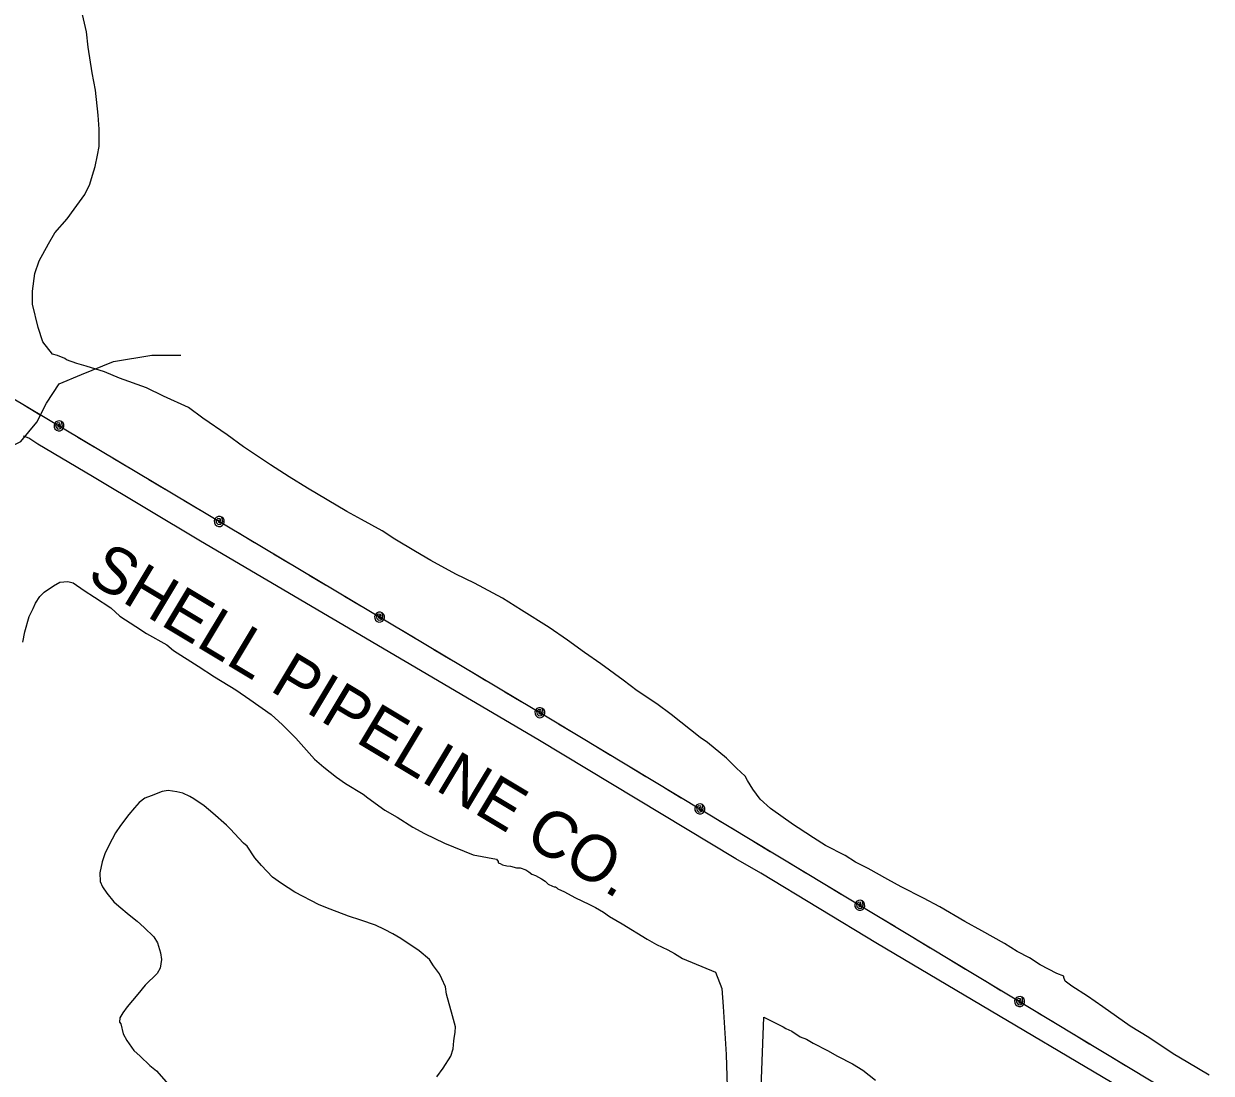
# Model space of a CAD drawing. Extents: x 3355677 to 3393573, y 612928 to 638357.
# Drawn here: x 3382938 to 3385063, y 630906 to 632784 of the extents above; entities that cross this region are included whole.
import ezdxf

# ---------------------------------------------------------------- set-up
doc = ezdxf.new("R2010")
doc.units = 0
for name, color, linetype in [('V-ROAD-CNTR', 7, 'Continuous'), ('V-SITE-VEGE', 7, 'Continuous'), ('V-TOPO-SHOR', 7, 'Continuous'), ('V-UTIL-IDEN', 7, 'Continuous'), ('V-UTIL-LINE', 7, 'Continuous')]:
    doc.layers.add(name, color=color, linetype=linetype)

msp = doc.modelspace()

# ---------------------------------------------------------------- linework, layer by layer
at = {"layer": 'V-ROAD-CNTR'}
msp.add_spline([(3382717.9, 631509.3), (3382683, 631774.7), (3382645.6, 632061.1), (3382613.4, 632280.7), (3382607, 632336.9), (3382604.4, 632398.7), (3382603.4, 632508.7), (3382612.3, 632627.6), (3382654.5, 632927.5), (3382669.5, 633023.9), (3382682.6, 633148.8), (3382689, 633232), (3382692.9, 633407.4), (3382698.9, 633498.5), (3382707.2, 633527.5), (3382719.2, 633555.1), (3382736.7, 633581.7), (3382777.9, 633615.1), (3383029.9, 633741), (3383294, 633867.7), (3383400.4, 633901.1), (3383469.4, 633903.2), (3383518.6, 633883.7), (3383607.6, 633824.8), (3383746.8, 633756.4), (3383797.6, 633735.9), (3383849.3, 633690.5), (3383896.6, 633650.2), (3383949.4, 633607.3), (3384007.3, 633569.4), (3384064.9, 633557.2), (3384119.3, 633550.6), (3384167.5, 633588.4), (3384178.7, 633673.8), (3384210.8, 633866.5), (3384225.9, 634112.9), (3384238.7, 634424.3), (3384250.9, 634776.1), (3384254, 634833.1)], degree=3, dxfattribs=at)
at = {"layer": 'V-SITE-VEGE'}
for p, q in [((3383050.1, 632770.1), (3383042.9, 632800.9)), ((3383053, 632742.7), (3383050.1, 632770.1)), ((3383060.1, 632696.5), (3383053, 632742.7)), ((3383066.2, 632665.7), (3383060.1, 632696.5)), ((3383071.1, 632620.7), (3383066.2, 632665.7)), ((3383072.9, 632595.5), (3383071.1, 632620.7)), ((3383072.5, 632564.8), (3383072.9, 632595.5)), ((3383070, 632549.4), (3383072.5, 632564.8)), ((3383065.4, 632528.7), (3383070, 632549.4)), ((3383060.8, 632513.4), (3383065.4, 632528.7)), ((3383047.1, 632478.5), (3383056.1, 632497)), ((3383056.1, 632497), (3383060.8, 632513.4)), ((3383028.1, 632452.5), (3383047.1, 632478.5)), ((3382993.5, 632410.2), (3383015.8, 632435.1)), ((3383015.8, 632435.1), (3383028.1, 632452.5)), ((3382965.4, 632360.2), (3382982.3, 632390.6)), ((3382982.3, 632390.6), (3382993.5, 632410.2)), ((3382957.4, 632337.2), (3382965.4, 632360.2)), ((3382953.7, 632305.5), (3382957.4, 632337.2)), ((3382953.3, 632282.5), (3382953.7, 632305.5)), ((3382963.7, 632240.7), (3382953.3, 632282.5)), ((3382972.1, 632215.3), (3382963.7, 632240.7)), ((3382989.4, 632193.2), (3382972.1, 632215.3)), ((3382998.1, 632190.8), (3382989.4, 632193.2)), ((3383011.2, 632185.2), (3382998.1, 632190.8)), ((3383014.4, 632182.9), (3383011.2, 632185.2)), ((3383033, 632176.1), (3383014.4, 632182.9)), ((3383049.3, 632171.5), (3383033, 632176.1)), ((3383082.1, 632161.2), (3383049.3, 632171.5)), ((3383109.3, 632149.8), (3383082.1, 632161.2)), ((3383157.3, 632132.7), (3383109.3, 632149.8)), ((3383187.8, 632118), (3383157.3, 632132.7)), ((3383232.5, 632097.6), (3383187.8, 632118)), ((3383258.5, 632078.6), (3383232.5, 632097.6)), ((3383302, 632048.4), (3383258.5, 632078.6)), ((3383331.3, 632027.2), (3383302, 632048.4)), ((3383379.1, 631994.7), (3383331.3, 632027.2)), ((3383412.7, 631973.4), (3383379.1, 631994.7)), ((3383445.3, 631953.2), (3383412.7, 631973.4)), ((3383516, 631911.6), (3383445.3, 631953.2)), ((3383542.1, 631897), (3383516, 631911.6)), ((3383579.1, 631876.7), (3383542.1, 631897)), ((3383601.9, 631862.2), (3383579.1, 631876.7)), ((3383638.9, 631839.7), (3383601.9, 631862.2)), ((3383666.1, 631824), (3383638.9, 631839.7)), ((3383710.7, 631799.2), (3383666.1, 631824)), ((3383744.5, 631783.4), (3383710.7, 631799.2)), ((3383794.5, 631756.4), (3383744.5, 631783.4)), ((3383828.2, 631735.1), (3383794.5, 631756.4)), ((3383878.2, 631703.7), (3383828.2, 631735.1)), ((3383910.8, 631681.3), (3383878.2, 631703.7)), ((3383941.1, 631658.9), (3383910.8, 631681.3)), ((3383970.5, 631638.8), (3383941.1, 631658.9)), ((3384010.6, 631609.7), (3383970.5, 631638.8)), ((3384035.6, 631590.7), (3384010.6, 631609.7)), ((3384070.3, 631567.2), (3384035.6, 631590.7)), ((3384096.3, 631548.2), (3384070.3, 631567.2)), ((3384148.4, 631506.9), (3384096.3, 631548.2)), ((3384161.4, 631497.9), (3384148.4, 631506.9)), ((3384195, 631470), (3384161.4, 631497.9)), ((3384213.4, 631452.2), (3384195, 631470)), ((3384228.5, 631437.8), (3384213.4, 631452.2)), ((3384232.8, 631430), (3384228.5, 631437.8)), ((3384242.5, 631414.5), (3384232.8, 631430)), ((3384255.4, 631396.8), (3384242.5, 631414.5)), ((3384273.8, 631380.1), (3384255.4, 631396.8)), ((3384315, 631351), (3384273.8, 631380.1)), ((3384323.7, 631345.4), (3384315, 631351)), ((3384350.9, 631327.5), (3384323.7, 631345.4)), ((3384372.6, 631314), (3384350.9, 631327.5)), ((3384407.4, 631296), (3384372.6, 631314)), ((3384425.9, 631283.7), (3384407.4, 631296)), ((3384448.8, 631272.4), (3384425.9, 631283.7)), ((3384483.6, 631253.2), (3384448.8, 631272.4)), ((3384507.5, 631239.7), (3384483.6, 631253.2)), ((3384547.8, 631219.4), (3384507.5, 631239.7)), ((3384577.2, 631203.7), (3384547.8, 631219.4)), ((3384621.8, 631177.8), (3384577.2, 631203.7)), ((3384652.2, 631161), (3384621.8, 631177.8)), ((3384692.5, 631138.5), (3384652.2, 631161)), ((3384715.3, 631123.9), (3384692.5, 631138.5)), ((3384737.1, 631112.6), (3384715.3, 631123.9)), ((3384756.6, 631100.3), (3384737.1, 631112.6)), ((3384786, 631084.5), (3384756.6, 631100.3)), ((3384799.1, 631079.9), (3384786, 631084.5)), ((3384799.1, 631077.7), (3384799.1, 631079.9)), ((3384801.2, 631071.1), (3384799.1, 631077.7)), ((3384813.1, 631062.2), (3384801.2, 631071.1)), ((3384841.3, 631044.2), (3384813.1, 631062.2)), ((3384868.5, 631025.2), (3384841.3, 631044.2)), ((3384917.3, 630990.5), (3384868.5, 631025.2)), ((3384951, 630970.3), (3384917.3, 630990.5)), ((3384994.5, 630941.2), (3384951, 630970.3)), ((3385020.6, 630925.5), (3384994.5, 630941.2)), ((3385058.6, 630903), (3385020.6, 630925.5))]:
    msp.add_line(p, q, dxfattribs=at)
for points in [[(3382936, 631677.5), (3382939.6, 631696.1), (3382947.6, 631723.4), (3382954.4, 631737.6), (3382958.9, 631747.4), (3382966.8, 631759.3), (3382974.5, 631766.9), (3382991.2, 631778.7), (3383002.2, 631785.1), (3383016.5, 631786), (3383026.3, 631783.7), (3383045.9, 631770.3), (3383064.3, 631757.9), (3383093.7, 631738.9), (3383109.9, 631724.4), (3383138.1, 631705.4), (3383157.7, 631693), (3383193.6, 631672.8), (3383205.5, 631662.7), (3383250.1, 631634.7), (3383279.4, 631615.6), (3383317.4, 631592.1), (3383342.4, 631575.3), (3383380.4, 631548.4), (3383401, 631529.5), (3383424.8, 631506.1), (3383458.2, 631468.4), (3383474.5, 631453.9), (3383497.2, 631436), (3383513.5, 631424.8), (3383545, 631405.8), (3383553.7, 631399.1), (3383584.1, 631376.7), (3383605.9, 631364.3), (3383634.1, 631346.4), (3383654.8, 631335.1), (3383690.7, 631318.2), (3383741.9, 631297)], [(3383686.1, 631075.2), (3383681.9, 631084), (3383671.1, 631098.4), (3383663.6, 631109.5), (3383645.2, 631125.1), (3383612.6, 631147.5), (3383598.5, 631155.4), (3383583.2, 631163.3), (3383566.9, 631171.2), (3383540.7, 631180.3), (3383518.9, 631187.2), (3383486.2, 631199.7), (3383466.5, 631207.7), (3383423, 631230.2), (3383399.1, 631245.9), (3383382.8, 631257.1), (3383363.4, 631278.2), (3383351.5, 631291.5), (3383337.6, 631312.6), (3383331.1, 631318.1), (3383307.3, 631343.7), (3383300.8, 631350.4), (3383275.9, 631371.5), (3383260.7, 631384.9), (3383242.3, 631397.2), (3383234.7, 631401.7), (3383222.7, 631407.4), (3383211.8, 631409.7), (3383196.4, 631412.1), (3383185.4, 631410.1), (3383165.6, 631402.7), (3383154.6, 631398.5), (3383144.6, 631390.9), (3383135.7, 631381.2), (3383125.7, 631369.3), (3383111.1, 631349.8), (3383102.2, 631336.7)], [(3383102.2, 631336.7), (3383089.8, 631313.9), (3383083, 631298.6), (3383078.4, 631284.4), (3383073.8, 631264.8), (3383074.6, 631249.4), (3383078.9, 631239.5), (3383086.4, 631228.4), (3383099.3, 631212.9), (3383108, 631205.1), (3383126.4, 631189.5), (3383140.5, 631178.3), (3383153.5, 631167.2), (3383170.8, 631150.5), (3383177.2, 631139.4), (3383182.5, 631121.8), (3383184.5, 631109.7), (3383182.1, 631094.4), (3383176.5, 631084.6), (3383155.3, 631064.1), (3383141.9, 631047.8), (3383123, 631025.1), (3383115.2, 631014.2), (3383109.6, 631005.5), (3383109.4, 630997.8), (3383111.6, 630994.5), (3383115.7, 630976.9), (3383122.1, 630964.8), (3383135, 630947), (3383145.9, 630937), (3383163.2, 630920.3), (3383175.1, 630910.3), (3383196.7, 630885.9)], [(3383741.9, 631297), (3383783.5, 631289.5), (3383786.7, 631285), (3383786.7, 631282.8), (3383790, 631281.7), (3383794.3, 631279.4), (3383802, 631277.1), (3383808.5, 631277), (3383819.5, 631273.6), (3383826, 631273.5), (3383835.9, 631270.1), (3383841.3, 631266.7), (3383846.7, 631262.3), (3383853.3, 631260), (3383864.1, 631254.3), (3383870.7, 631249.9), (3383876.1, 631244.3), (3383883.7, 631240.9), (3383887, 631239.8), (3383889.2, 631239.7), (3383891.3, 631238.6), (3383893.5, 631236.4), (3383905.5, 631230.7), (3383924, 631220.6), (3383950.1, 631208.2), (3383961, 631202.5), (3383975.1, 631194.7), (3383986, 631186.8), (3384008.8, 631173.3), (3384053.4, 631146.4), (3384069.7, 631136.3), (3384090.4, 631127.2), (3384102.4, 631120.5), (3384116.7, 631111.8), (3384175.5, 631086.9), (3384186.7, 631058), (3384189.5, 631025.4), (3384194.5, 630939.8), (3384222.4, 630039.6)], [(3383677.1, 630899.9), (3383688.3, 630915.1), (3383701.7, 630936.8), (3383706.3, 630949.9), (3383707.6, 630964.2), (3383707.7, 630968.5), (3383710, 630979.5), (3383710.1, 630989.3), (3383704.9, 631009.1), (3383694.5, 631047.7), (3383692.5, 631060.9), (3383686.1, 631075.2)], [(3384257.5, 630880.5), (3384262.1, 631006.4), (3384296.9, 630989.1), (3384301.1, 630986.1), (3384312, 630981.6), (3384327.2, 630971.5), (3384338.1, 630966.9), (3384350.1, 630960.2), (3384376.2, 630946.7), (3384393.6, 630936.6), (3384420.8, 630923), (3384439.3, 630911.8), (3384462.1, 630893.9)]]:
    msp.add_lwpolyline(points, dxfattribs=at)
at = {"layer": 'V-TOPO-SHOR'}
msp.add_lwpolyline([(3382669.1, 632048.2), (3382772.1, 631996.6), (3382817.9, 631996.6), (3382863.7, 632002.4), (3382932.5, 632036.7), (3382961.1, 632071.1), (3382978.3, 632105.4), (3383001.2, 632139.8), (3383041.2, 632156.9), (3383098.5, 632179.8), (3383167.2, 632191.3), (3383218.7, 632191.3)], dxfattribs=at)
at = {"layer": 'V-UTIL-LINE'}
for points in [[(3375476.3, 636537), (3376180.1, 636123.2), (3377572.3, 635287.3), (3379039.2, 634423.8), (3380469, 633561.5), (3381192.3, 633135.3), (3382557.5, 632329.2), (3383883.2, 631538.5), (3385271.9, 630701.6), (3386423.6, 630728.6), (3387326, 630116.8)], [(3382938.2, 632102.1), (3382967.4, 632084.7)], [(3383000.9, 632064.7), (3383000.7, 632067.6), (3382998.9, 632066.1), (3382999.1, 632063.4), (3383001.8, 632062.2), (3383003.7, 632065), (3383002.6, 632069.6), (3382998.4, 632070.1), (3382994.9, 632066.7), (3382995.8, 632062.2), (3382999, 632059.1), (3383003.8, 632059.9), (3383006.9, 632064.4), (3383005.5, 632072.5), (3383002.2, 632073.6), (3382998.7, 632073.4), (3382995.5, 632071.9), (3382993.2, 632069.3), (3382992, 632066), (3382992.2, 632062.5), (3382993.7, 632059.3), (3382996.3, 632057), (3382999.6, 632055.8), (3383003.1, 632056), (3383006.3, 632057.5), (3383008.6, 632060.1), (3383009.8, 632063.4), (3383009.6, 632066.9), (3383008.1, 632070.1), (3383005.5, 632072.5)], [(3385069.5, 630779.6), (3384465.3, 631137.9), (3384256.5, 631264.5), (3384212.2, 631289.9), (3383857.9, 631503.4), (3383253.8, 631858.1), (3383060.8, 631973.9), (3382962.8, 632031.8), (3382946.9, 632042.7), (3382937.4, 632046.3)], [(3383034.4, 632044.7), (3383063.6, 632027.3)], [(3383097.9, 632006.8), (3383127.1, 631989.4)], [(3383161.5, 631968.9), (3383190.7, 631951.5)], [(3383225, 631931), (3383254.2, 631913.6)], [(3383287.7, 631893.6), (3383287.5, 631896.5), (3383285.7, 631895), (3383286, 631892.3), (3383288.7, 631891.1), (3383290.5, 631893.9), (3383289.5, 631898.5), (3383285.3, 631899), (3383281.7, 631895.6), (3383282.6, 631891.1), (3383285.9, 631888), (3383290.7, 631888.8), (3383293.8, 631893.3), (3383292.4, 631901.4), (3383289, 631902.5), (3383285.5, 631902.4), (3383282.4, 631900.8), (3383280, 631898.2), (3383278.8, 631894.9), (3383279, 631891.4), (3383280.5, 631888.2), (3383283.1, 631885.9), (3383286.4, 631884.7), (3383289.9, 631884.9), (3383293.1, 631886.4), (3383295.5, 631889), (3383296.6, 631892.3), (3383296.5, 631895.8), (3383295, 631899), (3383292.4, 631901.4)], [(3383321.2, 631873.6), (3383350.4, 631856.2)], [(3383384.8, 631835.7), (3383414, 631818.3)], [(3383448.3, 631797.8), (3383477.5, 631780.4)], [(3383511.9, 631759.9), (3383541.1, 631742.5)], [(3383574.6, 631722.5), (3383574.4, 631725.4), (3383572.6, 631723.9), (3383572.8, 631721.2), (3383575.5, 631720), (3383577.4, 631722.8), (3383576.3, 631727.4), (3383572.1, 631727.9), (3383568.6, 631724.5), (3383569.5, 631720), (3383572.7, 631716.9), (3383577.5, 631717.7), (3383580.6, 631722.2), (3383579.2, 631730.3), (3383575.9, 631731.4), (3383572.4, 631731.3), (3383569.2, 631729.7), (3383566.9, 631727.1), (3383565.7, 631723.8), (3383565.9, 631720.3), (3383567.4, 631717.2), (3383570, 631714.8), (3383573.3, 631713.6), (3383576.8, 631713.8), (3383580, 631715.3), (3383582.3, 631717.9), (3383583.5, 631721.2), (3383583.3, 631724.7), (3383581.8, 631727.9), (3383579.2, 631730.3)], [(3383608.1, 631702.6), (3383637.3, 631685.1)], [(3383671.6, 631664.6), (3383700.8, 631647.2)], [(3383735.2, 631626.7), (3383764.4, 631609.3)], [(3383798.7, 631588.8), (3383827.9, 631571.4)], [(3383861.4, 631551.4), (3383861.2, 631554.3), (3383859.4, 631552.8), (3383859.7, 631550.1), (3383862.4, 631548.9), (3383864.2, 631551.7), (3383863.2, 631556.3), (3383858.9, 631556.8), (3383855.4, 631553.4), (3383856.3, 631548.9), (3383859.6, 631545.8), (3383864.4, 631546.6), (3383867.4, 631551.1), (3383866, 631559.2), (3383862.7, 631560.3), (3383859.2, 631560.2), (3383856.1, 631558.7), (3383853.7, 631556), (3383852.5, 631552.7), (3383852.7, 631549.2), (3383854.2, 631546.1), (3383856.8, 631543.7), (3383860.1, 631542.5), (3383863.6, 631542.7), (3383866.8, 631544.2), (3383869.2, 631546.8), (3383870.3, 631550.1), (3383870.2, 631553.6), (3383868.7, 631556.8), (3383866, 631559.2)], [(3383894.9, 631531.4), (3383924, 631513.9)], [(3383958.3, 631493.2), (3383987.4, 631475.7)], [(3384021.7, 631455), (3384050.8, 631437.5)], [(3384085, 631416.8), (3384114.2, 631399.3)], [(3384147.6, 631379.2), (3384147.4, 631382), (3384145.6, 631380.6), (3384145.8, 631377.8), (3384148.5, 631376.6), (3384150.4, 631379.4), (3384149.3, 631384), (3384145.1, 631384.5), (3384141.6, 631381.1), (3384142.5, 631376.6), (3384145.7, 631373.6), (3384150.5, 631374.3), (3384153.6, 631378.8), (3384152.2, 631386.9), (3384148.9, 631388.1), (3384145.4, 631387.9), (3384142.2, 631386.4), (3384139.9, 631383.8), (3384138.7, 631380.5), (3384138.8, 631377), (3384140.3, 631373.8), (3384142.9, 631371.4), (3384146.2, 631370.3), (3384149.7, 631370.4), (3384152.9, 631371.9), (3384155.3, 631374.5), (3384156.5, 631377.8), (3384156.3, 631381.3), (3384154.8, 631384.5), (3384152.2, 631386.9)], [(3384181, 631359), (3384210.1, 631341.5)], [(3384244.4, 631320.8), (3384273.5, 631303.3)], [(3384307.7, 631282.6), (3384336.9, 631265.1)], [(3384371.1, 631244.4), (3384400.2, 631226.9)], [(3384433.6, 631206.8), (3384433.5, 631209.6), (3384431.6, 631208.2), (3384431.9, 631205.5), (3384434.6, 631204.2), (3384436.4, 631207.1), (3384435.4, 631211.6), (3384431.2, 631212.1), (3384427.7, 631208.8), (3384428.5, 631204.3), (3384431.8, 631201.2), (3384436.5, 631201.9), (3384439.7, 631206.4), (3384438.3, 631214.5), (3384435, 631215.7), (3384431.5, 631215.5), (3384428.3, 631214), (3384425.9, 631211.4), (3384424.7, 631208.1), (3384424.9, 631204.6), (3384426.4, 631201.4), (3384429, 631199.1), (3384432.3, 631197.9), (3384435.8, 631198), (3384439, 631199.5), (3384441.4, 631202.1), (3384442.5, 631205.4), (3384442.4, 631208.9), (3384440.9, 631212.1), (3384438.3, 631214.5)], [(3384467.1, 631186.6), (3384496.2, 631169.1)], [(3384530.4, 631148.4), (3384559.6, 631130.9)], [(3384593.8, 631110.3), (3384622.9, 631092.7)], [(3384657.2, 631072.1), (3384686.3, 631054.5)], [(3384719.7, 631034.4), (3384719.5, 631037.3), (3384717.7, 631035.8), (3384718, 631033.1), (3384720.6, 631031.8), (3384722.5, 631034.7), (3384721.5, 631039.2), (3384717.3, 631039.7), (3384713.7, 631036.4), (3384714.6, 631031.9), (3384717.8, 631028.8), (3384722.6, 631029.5), (3384725.7, 631034.1), (3384724.4, 631042.1), (3384721.1, 631043.3), (3384717.6, 631043.1), (3384714.4, 631041.6), (3384712, 631039), (3384710.8, 631035.7), (3384711, 631032.2), (3384712.5, 631029), (3384715.1, 631026.7), (3384718.4, 631025.5), (3384721.9, 631025.6), (3384725.1, 631027.1), (3384727.4, 631029.7), (3384728.6, 631033), (3384728.5, 631036.5), (3384727, 631039.7), (3384724.4, 631042.1)], [(3384753.1, 631014.3), (3384782.3, 630996.7)], [(3384816.5, 630976.1), (3384845.6, 630958.5)], [(3384879.9, 630937.9), (3384909, 630920.3)]]:
    msp.add_lwpolyline(points, dxfattribs=at)

# ---------------------------------------------------------------- texts
at = {"layer": 'V-UTIL-IDEN'}
msp.add_text('SHELL PIPELINE CO.', height=83, rotation=329.0194, dxfattribs=at).set_placement((3383048, 631789.1))

doc.saveas('drawing.dxf')
